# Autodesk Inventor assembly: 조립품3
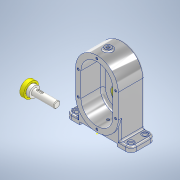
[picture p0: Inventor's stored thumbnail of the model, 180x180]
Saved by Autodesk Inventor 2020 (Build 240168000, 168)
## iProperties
Created: 2021-05
Part Number: 조립품3
Document SubType Name: Assembly
Designer: Owner
Author: Owner
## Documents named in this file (5)
- C:\Users\Owner\Desktop\710507V1001\조립품3.iam
- C:\Users\Owner\Desktop\710507V1001\본체.ipt
- C:\Users\Owner\Desktop\710507V1001\베어링 6001.ipt
- 베어링 6001.ipt
- C:\Users\Owner\Desktop\710507V1001\축 B.ipt
